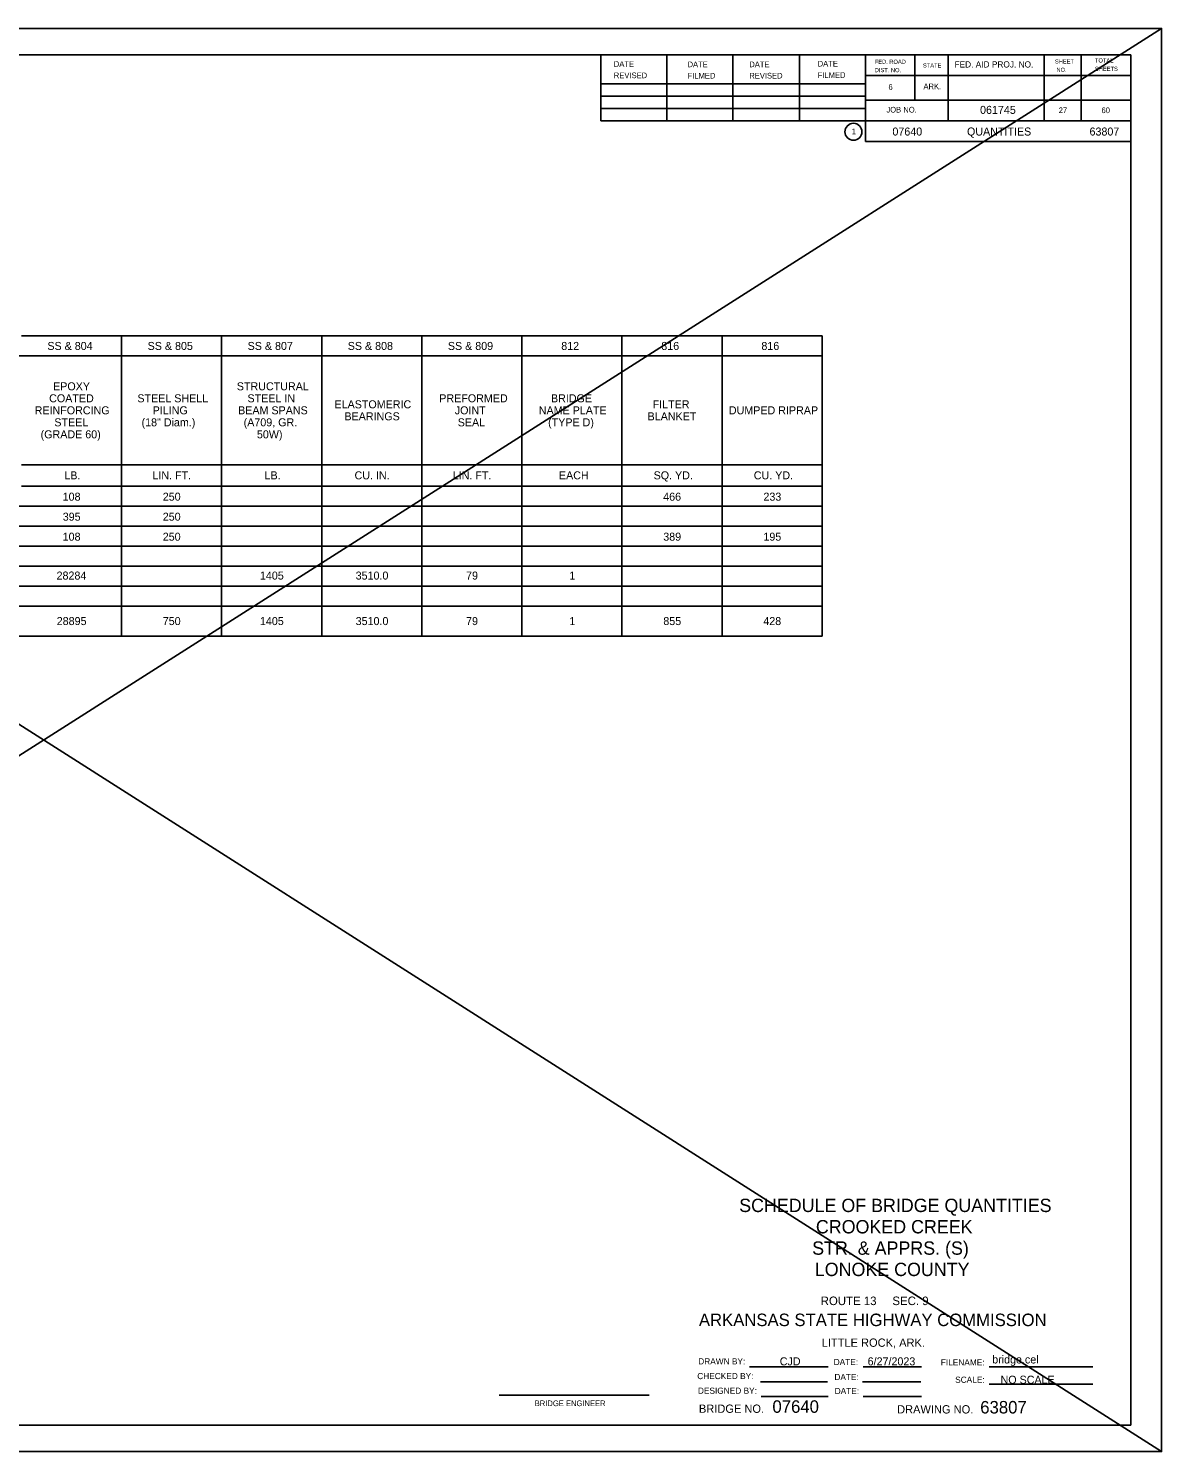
# Model space of a CAD drawing. Extents: x 1390434.7 to 1390467.9, y 1966884.5 to 1966897.9.
# Drawn here: x 1390440.2 to 1390445.86, y 1966890.78 to 1966897.89 of the extents above; entities that cross this region are included whole.
import ezdxf

# ---------------------------------------------------------------- set-up
doc = ezdxf.new("R2010")
doc.units = 0
for name, color, linetype in [('B_Border', 7, 'Continuous'), ('B_Detail_Work', 7, 'Continuous'), ('B_No_Plot', 7, 'Continuous'), ('Default', 7, 'Continuous')]:
    doc.layers.add(name, color=color, linetype=linetype)

msp = doc.modelspace()

# ---------------------------------------------------------------- linework, layer by layer
at = {"layer": 'B_Border'}
for p, q in [((1390435.1658, 1966897.7561), (1390445.7041, 1966897.7561)), ((1390443.0558, 1966897.7561), (1390443.0558, 1966897.4261)), ((1390443.3858, 1966897.4261), (1390443.3858, 1966897.7561)), ((1390443.7158, 1966897.4261), (1390443.7158, 1966897.7561)), ((1390444.0475, 1966897.4261), (1390444.0475, 1966897.7561)), ((1390444.3775, 1966897.3228), (1390444.3775, 1966897.7561)), ((1390444.6241, 1966897.5294), (1390444.6241, 1966897.7561)), ((1390444.7908, 1966897.4261), (1390444.7908, 1966897.7561)), ((1390445.2708, 1966897.7561), (1390445.2708, 1966897.4261)), ((1390445.4558, 1966897.7561), (1390445.4558, 1966897.4261)), ((1390445.7041, 1966890.9078), (1390445.7041, 1966897.7561)), ((1390444.3758, 1966897.6111), (1390443.0558, 1966897.6111)), ((1390445.7041, 1966897.6528), (1390444.3775, 1966897.6528)), ((1390444.3775, 1966897.5494), (1390443.0558, 1966897.5494)), ((1390445.7041, 1966897.5294), (1390444.3775, 1966897.5294)), ((1390444.3775, 1966897.4878), (1390443.0558, 1966897.4878)), ((1390445.7041, 1966897.4261), (1390443.0558, 1966897.4261)), ((1390444.3775, 1966897.3228), (1390445.7041, 1966897.3228)), ((1390443.7991, 1966891.1994), (1390444.1908, 1966891.1994)), ((1390444.3658, 1966891.1994), (1390444.6575, 1966891.1994)), ((1390444.9958, 1966891.1994), (1390445.5141, 1966891.1994)), ((1390443.8541, 1966891.1244), (1390444.1875, 1966891.1244)), ((1390444.3625, 1966891.1244), (1390444.6541, 1966891.1244)), ((1390442.5475, 1966891.0578), (1390443.2975, 1966891.0578)), ((1390443.8575, 1966891.0511), (1390444.1908, 1966891.0511)), ((1390444.3658, 1966891.0511), (1390444.6575, 1966891.0511)), ((1390444.9958, 1966891.1128), (1390445.5141, 1966891.1128)), ((1390445.7041, 1966890.9078), (1390435.1658, 1966890.9078))]:
    msp.add_line(p, q, dxfattribs=at)
msp.add_circle((1390444.3178, 1966897.3716), 0.0425, dxfattribs=at)
at = {"layer": 'B_No_Plot'}
msp.add_lwpolyline([(1390434.6899, 1966897.8879), (1390445.8566, 1966897.8879), (1390445.8566, 1966890.7759), (1390434.6899, 1966890.7759)], close=True, dxfattribs=at)
at = {"layer": 'Default'}
for p, q in [((1390434.6899, 1966897.8879), (1390445.8566, 1966890.7759)), ((1390445.8566, 1966897.8879), (1390434.6899, 1966890.7759)), ((1390440.1616, 1966896.3513), (1390440.6616, 1966896.3513)), ((1390440.6616, 1966896.3513), (1390440.6616, 1966894.8513)), ((1390440.6616, 1966896.3513), (1390441.1616, 1966896.3513)), ((1390441.1616, 1966896.3513), (1390441.1616, 1966894.8513)), ((1390441.1616, 1966896.3513), (1390441.6616, 1966896.3513)), ((1390441.6616, 1966896.3513), (1390441.6616, 1966894.8513)), ((1390441.6616, 1966896.3513), (1390442.1616, 1966896.3513)), ((1390442.1616, 1966896.3513), (1390442.1616, 1966894.8513)), ((1390442.1616, 1966896.3513), (1390442.6616, 1966896.3513)), ((1390442.6616, 1966896.3513), (1390442.6616, 1966894.8513)), ((1390442.6616, 1966896.3513), (1390443.1616, 1966896.3513)), ((1390443.1616, 1966896.3513), (1390443.1616, 1966894.8513)), ((1390443.1616, 1966896.3513), (1390443.6616, 1966896.3513)), ((1390443.6616, 1966896.3513), (1390443.6616, 1966894.8513)), ((1390443.6616, 1966896.3513), (1390444.1616, 1966896.3513)), ((1390444.1616, 1966896.3513), (1390444.1616, 1966894.8513)), ((1390436.6616, 1966896.2513), (1390444.1616, 1966896.2513)), ((1390440.1616, 1966895.7079), (1390440.6616, 1966895.7079)), ((1390440.6616, 1966895.7079), (1390441.1616, 1966895.7079)), ((1390441.1616, 1966895.7079), (1390441.6616, 1966895.7079)), ((1390441.6616, 1966895.7079), (1390442.1616, 1966895.7079)), ((1390442.1616, 1966895.7079), (1390442.6616, 1966895.7079)), ((1390442.6616, 1966895.7079), (1390443.1616, 1966895.7079)), ((1390443.1616, 1966895.7079), (1390443.6616, 1966895.7079)), ((1390443.6616, 1966895.7079), (1390444.1616, 1966895.7079)), ((1390440.1616, 1966895.6013), (1390440.6616, 1966895.6013)), ((1390440.6616, 1966895.6013), (1390441.1616, 1966895.6013)), ((1390441.1616, 1966895.6013), (1390441.6616, 1966895.6013)), ((1390441.6616, 1966895.6013), (1390442.1616, 1966895.6013)), ((1390442.1616, 1966895.6013), (1390442.6616, 1966895.6013)), ((1390442.6616, 1966895.6013), (1390443.1616, 1966895.6013)), ((1390443.1616, 1966895.6013), (1390443.6616, 1966895.6013)), ((1390443.6616, 1966895.6013), (1390444.1616, 1966895.6013)), ((1390435.6616, 1966895.5013), (1390444.1616, 1966895.5013)), ((1390435.6616, 1966895.4013), (1390444.1616, 1966895.4013)), ((1390435.6616, 1966895.3013), (1390444.1616, 1966895.3013)), ((1390435.6616, 1966895.2013), (1390444.1616, 1966895.2013)), ((1390435.6616, 1966895.1013), (1390444.1616, 1966895.1013)), ((1390435.6616, 1966895.0013), (1390444.1616, 1966895.0013)), ((1390435.6616, 1966894.8513), (1390444.1616, 1966894.8513))]:
    msp.add_line(p, q, dxfattribs=at)

# ---------------------------------------------------------------- texts
at = {"layer": 'B_Border'}
for s, height, p in [('FED. ROAD', 0.02066, (1390444.4241, 1966897.7111)), ('SHEET', 0.02066, (1390445.3241, 1966897.7128)), ('TOTAL', 0.02066, (1390445.5241, 1966897.7178)), ('DATE', 0.02833, (1390443.1208, 1966897.6961)), ('REVISED', 0.02833, (1390443.1208, 1966897.6394)), ('DATE', 0.02833, (1390443.4891, 1966897.6944)), ('FILMED', 0.02833, (1390443.4891, 1966897.6378)), ('DATE', 0.02833, (1390443.7975, 1966897.6944)), ('REVISED', 0.02833, (1390443.7975, 1966897.6378)), ('DATE', 0.02833, (1390444.1391, 1966897.6978)), ('FILMED', 0.02833, (1390444.1391, 1966897.6411)), ('DIST. NO.', 0.02066, (1390444.4241, 1966897.6694)), ('STATE', 0.02066, (1390444.665, 1966897.6928)), ('FED. AID PROJ. NO.', 0.031, (1390444.8225, 1966897.6928)), (' NO.', 0.02066, (1390445.3241, 1966897.6711)), ('SHEETS', 0.02066, (1390445.5241, 1966897.6761)), ('6', 0.0283, (1390444.4925, 1966897.5811)), ('ARK.', 0.02833, (1390444.6675, 1966897.5844)), ('JOB NO.', 0.02833, (1390444.4825, 1966897.4678)), ('061745', 0.04, (1390444.9502, 1966897.4611)), ('27', 0.02833, (1390445.3431, 1966897.4649)), ('60', 0.02833, (1390445.5569, 1966897.4649)), ('1', 0.0283, (1390444.3089, 1966897.3594)), ('07640', 0.04, (1390444.5124, 1966897.3528)), ('QUANTITIES', 0.04, (1390444.8849, 1966897.3528)), ('63807', 0.04, (1390445.497, 1966897.3528)), ('SS & 804', 0.04, (1390440.2913, 1966896.2813)), ('SS & 805', 0.04, (1390440.7921, 1966896.2813)), ('SS & 809', 0.04, (1390442.2918, 1966896.2813)), ('812', 0.04, (1390442.8582, 1966896.2813)), ('816', 0.04, (1390443.3579, 1966896.2813)), ('816', 0.04, (1390443.8579, 1966896.2813)), ('STEEL SHELL', 0.04, (1390440.7408, 1966896.0196)), ('PILING', 0.04, (1390440.8171, 1966895.9596)), ('(18" Diam.)', 0.04, (1390440.7618, 1966895.8996)), ('LIN. FT.', 0.04, (1390440.8162, 1966895.6346)), ('EACH', 0.04, (1390442.8466, 1966895.6346)), ('SQ. YD.', 0.04, (1390443.3196, 1966895.6346)), ('CU. YD.', 0.04, (1390443.8199, 1966895.6346)), ('108', 0.04, (1390440.3676, 1966895.528)), ('250', 0.04, (1390440.8677, 1966895.528)), ('466', 0.04, (1390443.3675, 1966895.528)), ('233', 0.04, (1390443.8681, 1966895.528)), ('395', 0.04, (1390440.368, 1966895.428)), ('250', 0.04, (1390440.8677, 1966895.428)), ('108', 0.04, (1390440.3676, 1966895.328)), ('250', 0.04, (1390440.8677, 1966895.328)), ('389', 0.04, (1390443.3677, 1966895.328)), ('195', 0.04, (1390443.868, 1966895.328)), ('28284', 0.04, (1390440.3372, 1966895.1337)), ('1405', 0.04, (1390441.353, 1966895.1337)), ('28895', 0.04, (1390440.338, 1966894.9063)), ('750', 0.04, (1390440.8677, 1966894.9063)), ('428', 0.04, (1390443.8676, 1966894.9063)), ('ROUTE 13     SEC. 9', 0.04266, (1390444.1541, 1966891.5078)), ('ARKANSAS STATE HIGHWAY COMMISSION', 0.06233, (1390443.5458, 1966891.4028)), ('LITTLE ROCK, ARK.', 0.04133, (1390444.1591, 1966891.2994)), ('bridge.cel', 0.04, (1390445.0108, 1966891.2161)), ('DRAWN BY:', 0.031, (1390443.5425, 1966891.2111)), ('CJD', 0.04, (1390443.9496, 1966891.2066)), ('DATE:', 0.031, (1390444.2191, 1966891.2078)), ('6/27/2023', 0.04, (1390444.3887, 1966891.2066)), ('FILENAME:', 0.031, (1390444.7541, 1966891.2061)), ('CHECKED BY:', 0.031, (1390443.5375, 1966891.1378)), ('DATE:', 0.031, (1390444.2225, 1966891.1328)), ('SCALE:', 0.031, (1390444.8258, 1966891.1194)), ('NO SCALE', 0.04, (1390445.0525, 1966891.1149)), ('DESIGNED BY:', 0.031, (1390443.5408, 1966891.0644)), ('DATE:', 0.031, (1390444.2241, 1966891.0628)), ('BRIDGE ENGINEER', 0.02833, (1390442.7258, 1966891.0028)), ('BRIDGE NO.', 0.04133, (1390443.5458, 1966890.9694)), ('DRAWING NO.', 0.04133, (1390444.5358, 1966890.9661))]:
    msp.add_text(s, height=height, dxfattribs=at).set_placement(p)
for s, p in [('SS & 807', (1390441.2916, 1966896.2813)), ('SS & 808', (1390441.7916, 1966896.2813)), ('EPOXY', (1390440.3198, 1966896.0796)), ('STRUCTURAL', (1390441.2376, 1966896.0796)), ('COATED', (1390440.3001, 1966896.0196)), ('STEEL IN', (1390441.2908, 1966896.0196)), ('ELASTOMERIC', (1390441.7254, 1966895.9896)), ('PREFORMED ', (1390442.2489, 1966896.0196)), ('BRIDGE', (1390442.8068, 1966896.0196)), ('FILTER', (1390443.3146, 1966895.9896)), ('REINFORCING', (1390440.2277, 1966895.9596)), ('BEAM SPANS', (1390441.244, 1966895.9596)), ('BEARINGS', (1390441.7751, 1966895.9296)), ('JOINT ', (1390442.3263, 1966895.9596)), ('NAME PLATE', (1390442.7459, 1966895.9596)), ('BLANKET', (1390443.2895, 1966895.9296)), ('DUMPED RIPRAP', (1390443.6954, 1966895.9596)), ('(GRADE 60)', (1390440.2576, 1966895.8396)), ('STEEL', (1390440.326, 1966895.8996)), ('(A709, GR.', (1390441.2717, 1966895.8996)), ('50W)', (1390441.338, 1966895.8396)), ('SEAL', (1390442.341, 1966895.8996)), ('(TYPE D)', (1390442.7925, 1966895.8996)), ('LB.', (1390440.376, 1966895.6346)), ('LB.', (1390441.376, 1966895.6346)), ('CU. IN.', (1390441.8257, 1966895.6346)), ('LIN. FT.', (1390442.3162, 1966895.6346)), ('3510.0', (1390441.8312, 1966895.1337)), ('79', (1390442.3827, 1966895.1337)), ('1', (1390442.8988, 1966895.1337)), ('1405', (1390441.353, 1966894.9063)), ('3510.0', (1390441.8312, 1966894.9063)), ('79', (1390442.3827, 1966894.9063)), ('1', (1390442.8988, 1966894.9063)), ('855', (1390443.368, 1966894.9063))]:
    msp.add_text(s, height=0.04, rotation=360, dxfattribs=at).set_placement(p)
at = {"layer": 'B_Detail_Work'}
for s, height, p in [('SCHEDULE OF BRIDGE QUANTITIES', 0.066666, (1390443.747, 1966891.9728)), ('CROOKED CREEK', 0.066666, (1390444.1301, 1966891.8661)), ('STR. & APPRS. (S)', 0.066666, (1390444.1115, 1966891.7594)), ('LONOKE COUNTY', 0.066666, (1390444.1247, 1966891.6528)), ('07640', 0.0625, (1390443.913, 1966890.9694)), ('63807', 0.0625, (1390444.951, 1966890.9661))]:
    msp.add_text(s, height=height, dxfattribs=at).set_placement(p)

doc.saveas('drawing.dxf')
